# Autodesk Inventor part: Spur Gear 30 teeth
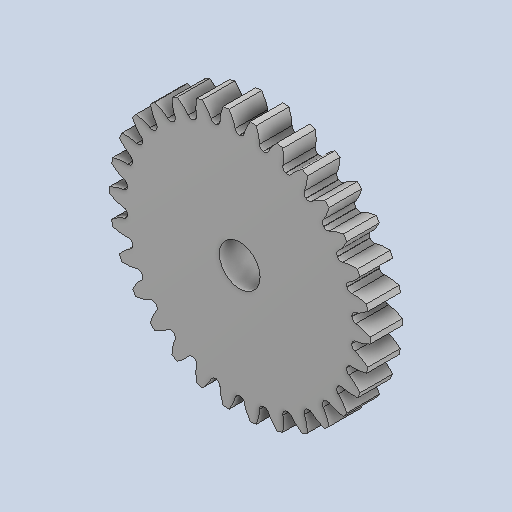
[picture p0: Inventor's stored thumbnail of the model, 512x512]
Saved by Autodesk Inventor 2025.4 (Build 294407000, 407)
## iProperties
Created: 2026-05
Part Number: Spur Gear 30 teeth
Material: Generic
Description: Spur Gear; Module: 1.0; Num Teeth: 30; Pressure Angle: 20.0; Backlash: 0.00 mm
Document SubType Name: Modeling
Designer: AdminForWorker
Density: 1 g/cm^3
Appearance: Default
Title: Spur Gear 30 teeth
Author: AdminForWorker
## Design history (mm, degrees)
feature "Body1"
body "Solid1"
